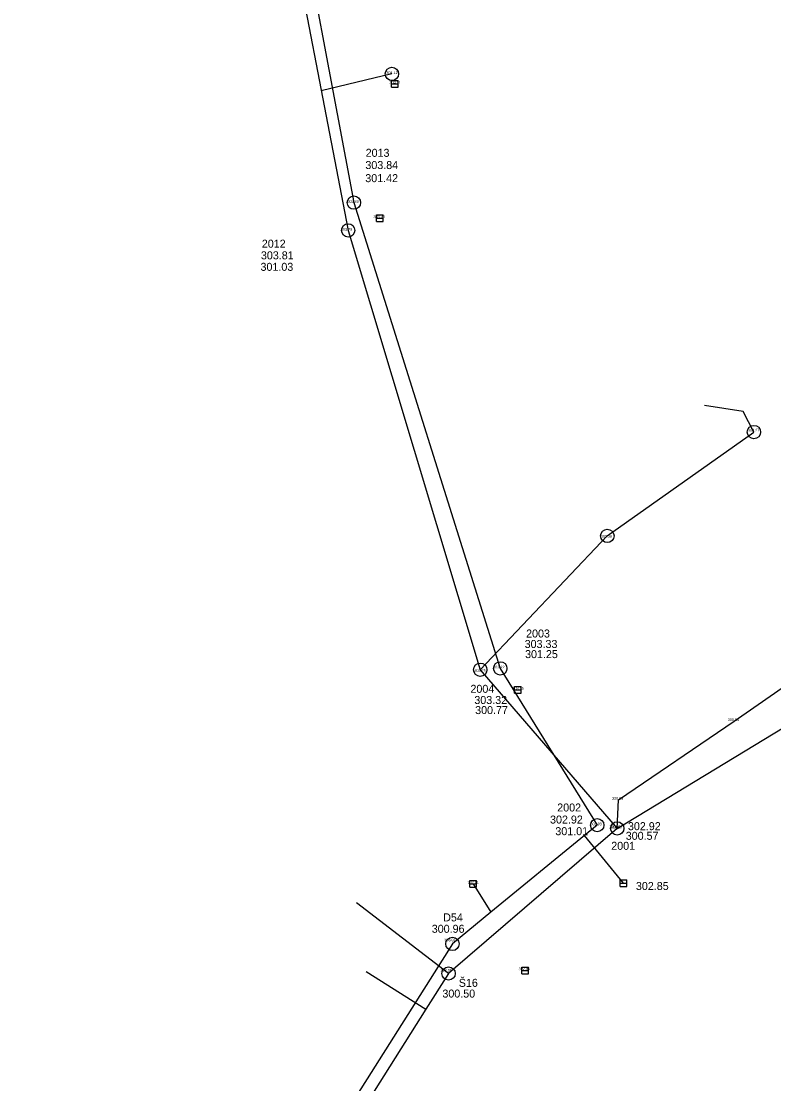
# Model space of a CAD drawing. Extents: x -734099 to -733912, y -1053676 to -1053434.
# Drawn here: x -734087.7 to -734031.4, y -1053634.7 to -1053555.1 of the extents above; entities that cross this region are included whole.
import ezdxf

# ---------------------------------------------------------------- set-up
doc = ezdxf.new("R2010")
doc.units = 0
for name, color, linetype in [('D-kanalizace', 7, 'Continuous'), ('D-ostatni_POPIS', 7, 'Continuous'), ('D-sachta', 7, 'Continuous'), ('D-ul_vpust', 7, 'Continuous'), ('DaS-VYSKY', 7, 'Continuous'), ('S-DIGI-kanalizace', 7, 'Continuous'), ('S-DIGI-sachta', 7, 'Continuous'), ('S-kanalizace', 7, 'Continuous'), ('S-ostatni_POPIS', 7, 'Continuous'), ('S-sachta', 7, 'Continuous'), ('S-VYTLAK-VYSKY', 7, 'Continuous'), ('S-VYTLAK_kanalizace', 7, 'Continuous')]:
    doc.layers.add(name, color=color, linetype=linetype)

msp = doc.modelspace()

# ---------------------------------------------------------------- linework, layer by layer
at = {"layer": 'D-kanalizace'}
for points in [[(-734057.19, -1053460.85), (-734062.51, -1053493.33), (-734067.13, -1053518.49), (-734067.73, -1053542.43), (-734062.81, -1053568.67), (-734051.84, -1053603.59), (-734044.58, -1053615.35), (-734045.524, -1053616.125), (-734052.542, -1053621.881), (-734055.43, -1053624.25), (-734072.802, -1053651.768), (-734073.062, -1053652.179), (-734082.86, -1053667.7), (-734087.73, -1053675.58)], [(-734042.6, -1053619.69), (-734045.524, -1053616.125)], [(-734053.88, -1053619.74), (-734052.542, -1053621.881)]]:
    msp.add_lwpolyline(points, dxfattribs=at)
at = {"layer": 'D-sachta'}
for centre in [(-734062.81, -1053568.67), (-734051.84, -1053603.59), (-734044.58, -1053615.35), (-734055.43, -1053624.25)]:
    msp.add_circle(centre, 0.5, dxfattribs=at)
at = {"layer": 'D-ul_vpust'}
for p, q in [((-734060, -1053559.51), (-734059.5, -1053559.51)), ((-734060, -1053560.01), (-734060, -1053559.51)), ((-734060, -1053559.76), (-734059.5, -1053559.76)), ((-734060, -1053560.01), (-734059.5, -1053560.01)), ((-734059.5, -1053560.01), (-734059.5, -1053559.51)), ((-734061.119, -1053569.58), (-734060.619, -1053569.58)), ((-734061.119, -1053570.08), (-734061.119, -1053569.58)), ((-734060.619, -1053570.08), (-734060.619, -1053569.58)), ((-734061.119, -1053569.83), (-734060.619, -1053569.83)), ((-734061.119, -1053570.08), (-734060.619, -1053570.08)), ((-734050.77, -1053604.94), (-734050.27, -1053604.94)), ((-734050.77, -1053605.44), (-734050.77, -1053604.94)), ((-734050.77, -1053605.19), (-734050.27, -1053605.19)), ((-734050.77, -1053605.44), (-734050.27, -1053605.44)), ((-734050.27, -1053605.44), (-734050.27, -1053604.94)), ((-734054.13, -1053619.49), (-734053.63, -1053619.49)), ((-734054.13, -1053619.99), (-734054.13, -1053619.49)), ((-734054.13, -1053619.74), (-734053.63, -1053619.74)), ((-734053.63, -1053619.99), (-734053.63, -1053619.49)), ((-734042.85, -1053619.44), (-734042.35, -1053619.44)), ((-734042.85, -1053619.94), (-734042.85, -1053619.44)), ((-734042.85, -1053619.69), (-734042.35, -1053619.69)), ((-734042.35, -1053619.94), (-734042.35, -1053619.44)), ((-734054.13, -1053619.99), (-734053.63, -1053619.99)), ((-734042.85, -1053619.94), (-734042.35, -1053619.94)), ((-734050.22, -1053625.99), (-734049.72, -1053625.99)), ((-734050.22, -1053626.49), (-734050.22, -1053625.99)), ((-734049.72, -1053626.49), (-734049.72, -1053625.99)), ((-734050.22, -1053626.24), (-734049.72, -1053626.24)), ((-734050.22, -1053626.49), (-734049.72, -1053626.49))]:
    msp.add_line(p, q, dxfattribs=at)
at = {"layer": 'S-DIGI-kanalizace'}
msp.add_line((-734059.96, -1053559.02), (-734065.253, -1053560.277), dxfattribs=at)
for points in [[(-734053.34, -1053603.69), (-734043.823, -1053593.663), (-734032.838, -1053585.869), (-734033.649, -1053584.337), (-734036.544, -1053583.887)], [(-734043.08, -1053615.59), (-734022.5, -1053603.11), (-733992.133, -1053583.533), (-733990.7, -1053589.346), (-733990.251, -1053591.165)]]:
    msp.add_lwpolyline(points, dxfattribs=at)
at = {"layer": 'S-DIGI-sachta'}
for centre in [(-734032.838, -1053585.869), (-734043.823, -1053593.663)]:
    msp.add_circle(centre, 0.5, dxfattribs=at)
at = {"layer": 'S-kanalizace'}
for points in [[(-734056.33, -1053451.24), (-734063.1, -1053492.02), (-734067.93, -1053520.12), (-734068.46, -1053543.59), (-734063.24, -1053570.75), (-734053.34, -1053603.69), (-734043.08, -1053615.59)], [(-734043.08, -1053615.59), (-734055.72, -1053626.47)], [(-734055.72, -1053626.47), (-734062.61, -1053621.17)], [(-734055.72, -1053626.47), (-734057.409, -1053629.149), (-734072.485, -1053653.059), (-734072.87, -1053653.67), (-734077.279, -1053660.733), (-734086.738, -1053675.884)], [(-734061.88, -1053626.33), (-734057.409, -1053629.149)]]:
    msp.add_lwpolyline(points, dxfattribs=at)
at = {"layer": 'S-sachta'}
for centre in [(-734059.96, -1053559.02), (-734063.24, -1053570.75), (-734053.34, -1053603.69), (-734043.08, -1053615.59), (-734055.72, -1053626.47)]:
    msp.add_circle(centre, 0.5, dxfattribs=at)
at = {"layer": 'S-VYTLAK_kanalizace'}
msp.add_lwpolyline([(-734043.08, -1053615.59), (-734042.99, -1053613.44), (-734034.32, -1053607.54), (-734016.67, -1053595.27), (-734003.38, -1053586.26), (-733988.45, -1053576.22), (-733984.39, -1053576.26), (-733973.81, -1053575.4), (-733959.47, -1053574.93), (-733949.61, -1053575.5), (-733940.71, -1053576.82), (-733926.03, -1053580.18), (-733919.74, -1053582.14), (-733913.34, -1053585.55), (-733911.543, -1053586.88)], dxfattribs=at)

# ---------------------------------------------------------------- texts
at = {"layer": 'D-ostatni_POPIS'}
for s, p in [('2013', (-734061.929, -1053565.235)), ('303.84', (-734061.95, -1053566.153)), ('301.42', (-734061.957, -1053567.135)), ('2003', (-734049.909, -1053601.278)), ('303.33', (-734050.017, -1053602.063)), ('301.25', (-734049.986, -1053602.823)), ('2002', (-734047.577, -1053614.323)), ('302.92', (-734048.114, -1053615.228)), ('301.01', (-734047.718, -1053616.1)), ('302.85', (-734041.68, -1053620.21)), ('D54', (-734056.12, -1053622.564)), ('300.96', (-734056.977, -1053623.417))]:
    msp.add_text(s, height=0.6, dxfattribs=at).set_placement(p)
at = {"layer": 'DaS-VYSKY'}
for s, p in [('304.12', (-734060.376, -1053559.02)), ('304.11', (-734060.142, -1053559.76)), ('303.80', (-734063.291, -1053568.69)), ('303.74', (-734061.343, -1053569.83)), ('303.79', (-734063.783, -1053570.77)), ('303.27', (-734033.283, -1053585.83)), ('303.38', (-734044.313, -1053593.8)), ('303.25', (-734053.783, -1053603.85)), ('303.22', (-734052.373, -1053603.6)), ('303.15', (-734050.936, -1053605.19)), ('302.93', (-734045.083, -1053615.36)), ('302.90', (-734043.612, -1053615.62)), ('302.91', (-734054.29, -1053619.73)), ('303.01', (-734056.038, -1053624.05)), ('303.05', (-734056.321, -1053626.33)), ('302.96', (-734050.469, -1053626.22))]:
    msp.add_text(s, height=0.2, dxfattribs=at).set_placement(p)
at = {"layer": 'S-ostatni_POPIS'}
for s, p in [('2012', (-734069.709, -1053572.049)), ('303.81', (-734069.776, -1053572.922)), ('301.03', (-734069.806, -1053573.783)), ('2004', (-734054.078, -1053605.425)), ('303.32', (-734053.786, -1053606.264)), ('300.77', (-734053.726, -1053607.018)), ('300.57', (-734042.444, -1053616.445)), ('302.92', (-734042.279, -1053615.724)), ('2001', (-734043.53, -1053617.197)), ('Š16', (-734054.951, -1053627.472)), ('300.50', (-734056.179, -1053628.276))]:
    msp.add_text(s, height=0.6, dxfattribs=at).set_placement(p)
at = {"layer": 'S-VYTLAK-VYSKY'}
for s, p in [('300.54', (-734034.801, -1053607.54)), ('300.63', (-734043.476, -1053613.44)), ('300.65', (-734043.666, -1053615.56))]:
    msp.add_text(s, height=0.2, dxfattribs=at).set_placement(p)

doc.saveas('drawing.dxf')
